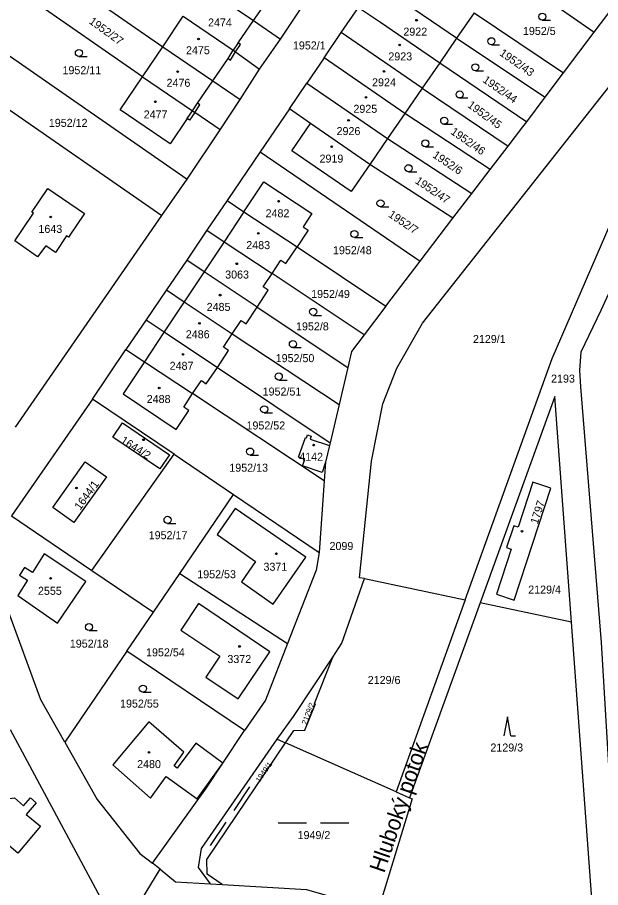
# Model space of a CAD drawing. Extents: x -679220 to -673243, y -1075091 to -1066557.
# Drawn here: x -676667.6 to -676543.7, y -1072885.5 to -1072700.8 of the extents above; entities that cross this region are included whole.
import ezdxf

# ---------------------------------------------------------------- set-up
doc = ezdxf.new("R2010")
doc.units = 0
for name, color, linetype in [('Hranice kat_území', 7, 'Continuous'), ('Hranice parcel', 7, 'Continuous'), ('Parcelní čísla', 7, 'Continuous'), ('Pop  PČ popisy', 7, 'Continuous'), ('Vnitřní kresba', 7, 'Continuous'), ('Značky budov', 7, 'Continuous'), ('Značky kultur', 7, 'Continuous')]:
    doc.layers.add(name, color=color, linetype=linetype)

msp = doc.modelspace()

# ---------------------------------------------------------------- linework, layer by layer
at = {"layer": 'Hranice kat_území'}
msp.add_line((-676626.56, -1072884.7), (-676624.07, -1072884.88), dxfattribs=at)
for points in [[(-676648.42, -1072899.8), (-676643.18, -1072891.41), (-676637.25, -1072881.62)], [(-676637.25, -1072881.62), (-676634, -1072884.28), (-676626.56, -1072884.7)], [(-676624.07, -1072884.88), (-676606.14, -1072885.94), (-676590.94, -1072890.3)]]:
    msp.add_lwpolyline(points, dxfattribs=at)
at = {"layer": 'Hranice parcel'}
for p, q in [((-676545.05, -1072703.94), (-676529.98, -1072683.88)), ((-676661.64, -1072689.7), (-676636.67, -1072707.03)), ((-676566.25, -1072689.13), (-676545.05, -1072703.94)), ((-676641, -1072713.4), (-676665.95, -1072696.04)), ((-676611.7, -1072705.39), (-676607.47, -1072699.05)), ((-676598.77, -1072704), (-676595.12, -1072698.65)), ((-676636.67, -1072707.03), (-676632.33, -1072700.52)), ((-676570.56, -1072699.78), (-676574.29, -1072705.21)), ((-676570.56, -1072699.78), (-676551.56, -1072712.54)), ((-676602.42, -1072709.36), (-676598.77, -1072704)), ((-676581.59, -1072715.82), (-676598.77, -1072704)), ((-676551.56, -1072712.54), (-676545.05, -1072703.94)), ((-676672.99, -1072706.39), (-676631.54, -1072735.13)), ((-676641, -1072713.4), (-676636.67, -1072707.03)), ((-676616.12, -1072711.79), (-676611.7, -1072705.39)), ((-676574.29, -1072705.21), (-676577.88, -1072710.43)), ((-676574.29, -1072705.21), (-676555.45, -1072717.68)), ((-676602.42, -1072709.36), (-676606.08, -1072714.73)), ((-676585.27, -1072721.17), (-676602.42, -1072709.36)), ((-676577.88, -1072710.43), (-676581.59, -1072715.82)), ((-676577.88, -1072710.43), (-676559.4, -1072722.91)), ((-676620.25, -1072718.2), (-676616.12, -1072711.79)), ((-676555.45, -1072717.68), (-676551.56, -1072712.54)), ((-676678.27, -1072714.14), (-676636.86, -1072742.81)), ((-676609.81, -1072720.21), (-676606.08, -1072714.73)), ((-676606.08, -1072714.73), (-676588.94, -1072726.51)), ((-676581.59, -1072715.82), (-676585.27, -1072721.17)), ((-676581.59, -1072715.82), (-676563.35, -1072728.09)), ((-676559.4, -1072722.91), (-676555.45, -1072717.68)), ((-676624.52, -1072724.61), (-676620.25, -1072718.2)), ((-676624.52, -1072724.61), (-676629.9, -1072720.95)), ((-676609.81, -1072720.21), (-676616.02, -1072729.34)), ((-676605.29, -1072723.32), (-676609.81, -1072720.21)), ((-676585.27, -1072721.17), (-676588.94, -1072726.51)), ((-676567.17, -1072733.09), (-676585.27, -1072721.17)), ((-676592.71, -1072731.98), (-676605.29, -1072723.32)), ((-676631.54, -1072735.13), (-676624.52, -1072724.61)), ((-676588.94, -1072726.51), (-676592.71, -1072731.98)), ((-676588.94, -1072726.51), (-676571.06, -1072738.18)), ((-676567.17, -1072733.09), (-676563.35, -1072728.09)), ((-676616.02, -1072729.34), (-676623.02, -1072739.65)), ((-676616.02, -1072729.34), (-676582.05, -1072752.56)), ((-676575.08, -1072743.43), (-676592.71, -1072731.98)), ((-676571.06, -1072738.18), (-676567.17, -1072733.09)), ((-676636.86, -1072742.81), (-676631.54, -1072735.13)), ((-676575.08, -1072743.43), (-676571.06, -1072738.18)), ((-676623.02, -1072739.65), (-676627.31, -1072745.97)), ((-676623.02, -1072739.65), (-676619.45, -1072742.02)), ((-676619.45, -1072742.02), (-676608.18, -1072749.51)), ((-676667.95, -1072787.75), (-676636.86, -1072742.81)), ((-676582.05, -1072752.56), (-676575.08, -1072743.43)), ((-676627.31, -1072745.97), (-676631.61, -1072752.3)), ((-676608.18, -1072749.51), (-676589.31, -1072762.05)), ((-676631.61, -1072752.3), (-676635.92, -1072758.64)), ((-676589.31, -1072762.05), (-676582.05, -1072752.56)), ((-676593.94, -1072768.16), (-676613.47, -1072755.18)), ((-676635.92, -1072758.64), (-676640.2, -1072764.96)), ((-676616.63, -1072762.29), (-676597.42, -1072775.1)), ((-676589.31, -1072762.05), (-676593.94, -1072768.16)), ((-676640.2, -1072764.96), (-676644.51, -1072771.31)), ((-676621.92, -1072767.93), (-676599.25, -1072782.97)), ((-676651.64, -1072781.8), (-676644.51, -1072771.31)), ((-676644.51, -1072771.31), (-676640.59, -1072773.9)), ((-676640.59, -1072773.9), (-676630.36, -1072780.66)), ((-676625.08, -1072775.07), (-676601.15, -1072791.08)), ((-676597.42, -1072775.1), (-676599.25, -1072782.97)), ((-676602.4, -1072799.14), (-676630.36, -1072780.66)), ((-676651.64, -1072781.8), (-676668.84, -1072806.61)), ((-676634.29, -1072793.54), (-676651.64, -1072781.8)), ((-676599.25, -1072782.97), (-676601.15, -1072791.08)), ((-676605.4, -1072790.31), (-676601.29, -1072791.69)), ((-676601.29, -1072791.69), (-676602.11, -1072795.21)), ((-676601.15, -1072791.08), (-676601.29, -1072791.69)), ((-676651.73, -1072818.21), (-676634.29, -1072793.54)), ((-676634.29, -1072793.54), (-676621.66, -1072802.09)), ((-676602.11, -1072795.21), (-676602.84, -1072797.38)), ((-676602.11, -1072795.21), (-676602.4, -1072799.14)), ((-676602.4, -1072799.14), (-676603.51, -1072814.38)), ((-676633.08, -1072818.86), (-676621.66, -1072802.09)), ((-676621.66, -1072802.09), (-676603.51, -1072814.38)), ((-676668.84, -1072806.61), (-676651.73, -1072818.21)), ((-676651.73, -1072818.21), (-676638.67, -1072827.06)), ((-676638.67, -1072827.06), (-676633.08, -1072818.86)), ((-676633.08, -1072818.86), (-676610.23, -1072833.74)), ((-676593.82, -1072819.93), (-676572.45, -1072824.42)), ((-676572.45, -1072824.42), (-676587.14, -1072865.18)), ((-676569.29, -1072825.08), (-676584.28, -1072866.45)), ((-676549.91, -1072829.16), (-676569.29, -1072825.08)), ((-676644.31, -1072835.34), (-676638.67, -1072827.06)), ((-676544.43, -1072903.83), (-676549.91, -1072829.16)), ((-676644.31, -1072835.34), (-676657.48, -1072854.68)), ((-676619.36, -1072852.17), (-676644.31, -1072835.34)), ((-676612.38, -1072854.04), (-676610.66, -1072854.8)), ((-676587.14, -1072865.18), (-676610.66, -1072854.8)), ((-676587.14, -1072865.18), (-676584.28, -1072866.45)), ((-676637.25, -1072881.62), (-676638.87, -1072880.32))]:
    msp.add_line(p, q, dxfattribs=at)
for points in [[(-676574.29, -1072705.21), (-676586.88, -1072696.55), (-676591.54, -1072693.39)], [(-676628.01, -1072694.22), (-676617.44, -1072701.46), (-676611.7, -1072705.39)], [(-676595.12, -1072698.65), (-676590.47, -1072701.78), (-676577.88, -1072710.43)], [(-676632.33, -1072700.52), (-676621.76, -1072707.76), (-676621.26, -1072708.1), (-676616.12, -1072711.79)], [(-676636.67, -1072707.03), (-676626.06, -1072714.25), (-676620.25, -1072718.2)], [(-676593.82, -1072819.93), (-676594.9, -1072819.74), (-676592.35, -1072795.01), (-676589.96, -1072782.82), (-676587.01, -1072775.23), (-676581.53, -1072765.66), (-676534.06, -1072705.55)], [(-676572.45, -1072824.42), (-676553.98, -1072773.19), (-676527.07, -1072711.02)], [(-676629.9, -1072720.95), (-676631, -1072722.56), (-676631.49, -1072722.23), (-676635.14, -1072727.59), (-676645.74, -1072720.38), (-676641, -1072713.4)], [(-676641, -1072713.4), (-676630.39, -1072720.62), (-676629.9, -1072720.95)], [(-676521.26, -1072714.56), (-676536.83, -1072748.24), (-676543.68, -1072763), (-676547.88, -1072771.84), (-676548.19, -1072775.66), (-676547.99, -1072779.21), (-676543.62, -1072833.49), (-676541.78, -1072863.16), (-676537.04, -1072892.63), (-676534.13, -1072903.67), (-676531.84, -1072907.69)], [(-676592.71, -1072731.98), (-676596.67, -1072737.74), (-676609.25, -1072729.08), (-676605.29, -1072723.32)], [(-676563.35, -1072728.09), (-676560.25, -1072724.03), (-676559.4, -1072722.91)], [(-676619.45, -1072742.02), (-676615.23, -1072735.65), (-676605.01, -1072742.43), (-676606.89, -1072745.26), (-676605.83, -1072745.96), (-676608.18, -1072749.51)], [(-676661.09, -1072737.1), (-676653.29, -1072742.44), (-676656.72, -1072747.46), (-676657.13, -1072747.18), (-676659.49, -1072750.66), (-676661.55, -1072749.26), (-676663.27, -1072751.6), (-676668.09, -1072748.23), (-676666.51, -1072745.81), (-676664.14, -1072742.34), (-676664.51, -1072742.09), (-676661.09, -1072737.1)], [(-676627.31, -1072745.97), (-676623.68, -1072748.39), (-676613.47, -1072755.18)], [(-676613.47, -1072755.18), (-676611.59, -1072752.35), (-676610.53, -1072753.05), (-676608.18, -1072749.51)], [(-676616.63, -1072762.29), (-676627.91, -1072754.77), (-676631.61, -1072752.3)], [(-676616.63, -1072762.29), (-676614.28, -1072758.71), (-676615.34, -1072758.01), (-676613.47, -1072755.18)], [(-676635.92, -1072758.64), (-676632.14, -1072761.15), (-676621.92, -1072767.93)], [(-676621.92, -1072767.93), (-676620.04, -1072765.1), (-676618.98, -1072765.8), (-676616.63, -1072762.29)], [(-676640.2, -1072764.96), (-676636.37, -1072767.52), (-676625.08, -1072775.07)], [(-676625.08, -1072775.07), (-676622.74, -1072771.46), (-676623.8, -1072770.76), (-676621.92, -1072767.93)], [(-676593.94, -1072768.16), (-676596.62, -1072771.69), (-676597.42, -1072775.1)], [(-676640.59, -1072773.9), (-676645.11, -1072780.71), (-676633.82, -1072788.29), (-676631.19, -1072784.21), (-676632.25, -1072783.51), (-676630.36, -1072780.66)], [(-676630.36, -1072780.66), (-676628.5, -1072777.85), (-676627.44, -1072778.55), (-676625.08, -1072775.07)], [(-676549.91, -1072829.16), (-676553.4, -1072781.23), (-676569.29, -1072825.08)], [(-676637.3, -1072796.6), (-676647.27, -1072789.89), (-676645.22, -1072786.88), (-676635.29, -1072793.63), (-676637.3, -1072796.6)], [(-676602.84, -1072797.38), (-676607, -1072795.98), (-676606.51, -1072794.61), (-676607.9, -1072794.11), (-676606.41, -1072789.96), (-676606.18, -1072790.04), (-676605.96, -1072789.43), (-676605.19, -1072789.68), (-676605.4, -1072790.31)], [(-676558.07, -1072799.45), (-676561.2, -1072809.04), (-676562.15, -1072808.73), (-676563.66, -1072813.34), (-676562.71, -1072813.65), (-676565.84, -1072823.24), (-676562.09, -1072824.47), (-676554.27, -1072800.74), (-676558.07, -1072799.45)], [(-676625.14, -1072810.57), (-676616.99, -1072816.29), (-676619.99, -1072820.64), (-676613.24, -1072825.34), (-676606.31, -1072815.39), (-676621.29, -1072805.01), (-676625.14, -1072810.57)], [(-676657.48, -1072854.68), (-676662.59, -1072845.67), (-676672.61, -1072818.42), (-676674.31, -1072814.63)], [(-676653.04, -1072820.52), (-676661.87, -1072814.7), (-676664.39, -1072818.66), (-676666.09, -1072817.58), (-676667.1, -1072819.18), (-676665.4, -1072820.26), (-676667.48, -1072823.53), (-676659.05, -1072829.38), (-676653.04, -1072820.52)], [(-676603.51, -1072814.38), (-676604.14, -1072818.11), (-676610.23, -1072833.74)], [(-676600.58, -1072836.58), (-676598.67, -1072833.66), (-676593.82, -1072819.93)], [(-676627.57, -1072840.88), (-676620.69, -1072845.47), (-676613.96, -1072835.46), (-676629.1, -1072825.24), (-676632.87, -1072830.87), (-676624.58, -1072836.4), (-676627.57, -1072840.88)], [(-676610.23, -1072833.74), (-676614.88, -1072845.71), (-676619.36, -1072852.17)], [(-676612.38, -1072854.04), (-676608.9, -1072849.18), (-676600.58, -1072836.58)], [(-676610.66, -1072854.8), (-676608.87, -1072852.15), (-676606.51, -1072852.11), (-676604.22, -1072846.49), (-676604.46, -1072846.44), (-676600.58, -1072836.58)], [(-676632.2, -1072856.81), (-676639.64, -1072850.31), (-676647.28, -1072859.5), (-676639.32, -1072866.57)], [(-676669.1, -1072851.93), (-676648.4, -1072890.46), (-676657.67, -1072902.92)], [(-676638.87, -1072880.32), (-676627.4, -1072864.33), (-676623.93, -1072859.09), (-676619.36, -1072852.17)], [(-676657.48, -1072854.68), (-676650.59, -1072866.83), (-676641.58, -1072878.26), (-676638.87, -1072880.32)], [(-676629.69, -1072854.84), (-676633.63, -1072860.19), (-676634.27, -1072859.71), (-676632.2, -1072856.81)], [(-676629.42, -1072866.71), (-676623.93, -1072859.09), (-676629.69, -1072854.84)], [(-676626.56, -1072884.7), (-676629.13, -1072881.23), (-676628.48, -1072877.23), (-676612.38, -1072854.04)], [(-676624.07, -1072884.88), (-676627.26, -1072882.71), (-676627.36, -1072879.59), (-676610.66, -1072854.8)], [(-676639.32, -1072866.57), (-676635.95, -1072861.95), (-676629.42, -1072866.71)], [(-676675.53, -1072868.64), (-676672.11, -1072864.65), (-676669.69, -1072866.66), (-676668.17, -1072866.46), (-676666.26, -1072868.17), (-676664.78, -1072866.45), (-676663.55, -1072867.5), (-676665.69, -1072869.99), (-676662.68, -1072872.49), (-676667.49, -1072878.19), (-676670.39, -1072875.75), (-676671.83, -1072875.84), (-676674.43, -1072878.94), (-676680.15, -1072874.17), (-676678.92, -1072872.66), (-676678.89, -1072871.16), (-676677.01, -1072868.92), (-676675.53, -1072868.64)], [(-676584.28, -1072866.45), (-676583.69, -1072866.71), (-676590.94, -1072890.3)]]:
    msp.add_lwpolyline(points, dxfattribs=at)
at = {"layer": 'Vnitřní kresba'}
for p, q in [((-676617.44, -1072701.46), (-676614.21, -1072696.83)), ((-676620.67, -1072706.18), (-676617.44, -1072701.46)), ((-676620.67, -1072706.18), (-676621.76, -1072707.76)), ((-676621.26, -1072708.1), (-676620.18, -1072706.52)), ((-676620.18, -1072706.52), (-676620.67, -1072706.18)), ((-676622.83, -1072709.5), (-676621.76, -1072707.76)), ((-676622.34, -1072709.84), (-676621.26, -1072708.1)), ((-676626.06, -1072714.25), (-676622.83, -1072709.5)), ((-676622.83, -1072709.5), (-676622.34, -1072709.84)), ((-676629.3, -1072719.01), (-676626.06, -1072714.25)), ((-676630.39, -1072720.62), (-676629.3, -1072719.01)), ((-676629.9, -1072720.95), (-676628.81, -1072719.34)), ((-676628.81, -1072719.34), (-676629.3, -1072719.01)), ((-676631.49, -1072722.23), (-676630.39, -1072720.62)), ((-676619.45, -1072742.02), (-676623.68, -1072748.39)), ((-676623.68, -1072748.39), (-676627.91, -1072754.77)), ((-676627.91, -1072754.77), (-676632.14, -1072761.15)), ((-676632.14, -1072761.15), (-676636.37, -1072767.52)), ((-676636.37, -1072767.52), (-676640.59, -1072773.9)), ((-676660.07, -1072804.85), (-676653.2, -1072795.1)), ((-676653.2, -1072795.1), (-676648.67, -1072798.32)), ((-676648.67, -1072798.32), (-676655.55, -1072808.04)), ((-676655.55, -1072808.04), (-676660.07, -1072804.85))]:
    msp.add_line(p, q, dxfattribs=at)
at = {"layer": 'Značky budov'}
for centre in [(-676582.79, -1072701.37), (-676629.09, -1072705.36), (-676586.37, -1072706.62), (-676633.53, -1072712.29), (-676589.69, -1072712.25), (-676593.53, -1072717.75), (-676638.28, -1072718.69), (-676597.23, -1072722.61), (-676600.81, -1072728.23), (-676612.08, -1072739.8), (-676660.49, -1072743.15), (-676616.4, -1072746.63), (-676620.97, -1072753.09), (-676624.51, -1072759.74), (-676628.9, -1072765.71), (-676632.38, -1072772.31), (-676637.44, -1072779.45), (-676640.79, -1072790.45), (-676604.66, -1072791.59), (-676655.02, -1072800.7), (-676560.4, -1072809.87), (-676612.56, -1072814.66), (-676660.5, -1072819.87), (-676620.39, -1072834.34), (-676639.6, -1072856.82)]:
    msp.add_circle(centre, 0.175, dxfattribs=at)
at = {"layer": 'Značky kultur'}
for p, q in [((-676556.09, -1072701.36), (-676554.34, -1072701.36)), ((-676566.9, -1072706.58), (-676565.15, -1072706.58)), ((-676654.51, -1072709.07), (-676652.76, -1072709.07)), ((-676570.3, -1072712.11), (-676568.55, -1072712.11)), ((-676573.64, -1072717.88), (-676571.89, -1072717.88)), ((-676576.92, -1072723.47), (-676575.17, -1072723.47)), ((-676580.92, -1072728.26), (-676579.17, -1072728.26)), ((-676584.5, -1072733.55), (-676582.75, -1072733.55)), ((-676590.45, -1072740.99), (-676588.7, -1072740.99)), ((-676595.98, -1072747.51), (-676594.23, -1072747.51)), ((-676604.75, -1072764.03), (-676603, -1072764.03)), ((-676609.06, -1072770.89), (-676607.31, -1072770.89)), ((-676612.05, -1072777.76), (-676610.3, -1072777.76)), ((-676615.15, -1072784.73), (-676613.4, -1072784.73)), ((-676618.14, -1072793.7), (-676616.39, -1072793.7)), ((-676635.67, -1072808.2), (-676633.92, -1072808.2)), ((-676652.35, -1072830.96), (-676650.6, -1072830.96)), ((-676640.92, -1072844.03), (-676639.17, -1072844.03)), ((-676563.5, -1072849.28), (-676564.25, -1072853.28)), ((-676562.75, -1072853.28), (-676563.5, -1072849.28)), ((-676562.75, -1072853.28), (-676561.75, -1072853.28)), ((-676621.54, -1072869.13), (-676618.18, -1072864.15)), ((-676626.57, -1072876.59), (-676623.21, -1072871.61)), ((-676612.17, -1072871.79), (-676606.17, -1072871.79)), ((-676603.17, -1072871.79), (-676597.17, -1072871.79))]:
    msp.add_line(p, q, dxfattribs=at)
for centre in [(-676556.09, -1072700.61), (-676566.9, -1072705.83), (-676654.51, -1072708.32), (-676570.3, -1072711.36), (-676573.64, -1072717.13), (-676576.92, -1072722.72), (-676580.92, -1072727.51), (-676584.5, -1072732.8), (-676590.45, -1072740.24), (-676595.98, -1072746.76), (-676604.75, -1072763.28), (-676609.06, -1072770.14), (-676612.05, -1072777.01), (-676615.15, -1072783.98), (-676618.14, -1072792.95), (-676635.67, -1072807.45), (-676652.35, -1072830.21), (-676640.92, -1072843.28)]:
    msp.add_circle(centre, 0.75, dxfattribs=at)

# ---------------------------------------------------------------- texts
at = {"layer": 'Parcelní čísla'}
for s, height, rotation, p in [('1952/27', 1.7, 324, (-676652.5, -1072701.92)), ('1952/43', 1.7, 325, (-676565.31, -1072708.7)), ('1952/44', 1.7, 325, (-676568.89, -1072714.38)), ('1952/45', 1.7, 324, (-676572.12, -1072719.7)), ('1952/46', 1.7, 325, (-676575.69, -1072725.39)), ('1952/6', 1.7, 326, (-676579.53, -1072730.37)), ('1952/47', 1.7, 326, (-676583.24, -1072735.84)), ('1952/7', 1.7, 326, (-676588.93, -1072742.99)), ('1644/2', 1.7, 328, (-676645.8, -1072791.01)), ('1644/1', 1.7, 54, (-676654.22, -1072805.5)), ('1797', 1.7, 72, (-676557.07, -1072808.49)), ('2129/2', 1.14, 69, (-676606.18, -1072851.02)), ('1949/1', 1.14, 55, (-676616.15, -1072863.29))]:
    msp.add_text(s, height=height, rotation=rotation, dxfattribs=at).set_placement(p)
for s, p in [('2474', (-676627.08, -1072702.7)), ('2922', (-676585.59, -1072704.65)), ('1952/5', (-676560.2, -1072704.5)), ('2475', (-676631.76, -1072708.59)), ('1952/1', (-676609.05, -1072707.57)), ('2923', (-676588.78, -1072709.9)), ('1952/11', (-676657.99, -1072712.83)), ('2476', (-676635.89, -1072715.51)), ('2924', (-676592.24, -1072715.4)), ('2925', (-676596.2, -1072721.03)), ('2477', (-676640.75, -1072722.23)), ('1952/12', (-676660.89, -1072724.01)), ('2926', (-676599.78, -1072725.76)), ('2919', (-676603.4, -1072731.6)), ('2482', (-676614.86, -1072743.21)), ('1643', (-676663.1, -1072746.53)), ('2483', (-676618.96, -1072749.97)), ('1952/48', (-676600.54, -1072751.05)), ('3063', (-676623.44, -1072756.22)), ('1952/49', (-676605.18, -1072760.35)), ('2485', (-676627.37, -1072763.09)), ('1952/8', (-676608.39, -1072767.22)), ('2486', (-676631.8, -1072768.9)), ('2129/1', (-676570.82, -1072769.91)), ('1952/50', (-676612.71, -1072773.97)), ('2487', (-676635.23, -1072775.6)), ('2193', (-676554.22, -1072778.31)), ('2488', (-676640.1, -1072782.64)), ('1952/51', (-676615.48, -1072781.06)), ('1952/52', (-676618.91, -1072788.26)), ('4142', (-676607.71, -1072794.91)), ('1952/13', (-676622.56, -1072797.23)), ('1952/17', (-676639.68, -1072811.56)), ('2099', (-676601.28, -1072813.86)), ('3371', (-676615.3, -1072818.26)), ('1952/53', (-676629.37, -1072819.85)), ('2129/4', (-676559.08, -1072823.11)), ('2555', (-676663.2, -1072823.37)), ('1952/18', (-676656.43, -1072834.58)), ('1952/54', (-676640.24, -1072836.43)), ('3372', (-676622.97, -1072837.85)), ('2129/6', (-676593.16, -1072842.3)), ('1952/55', (-676645.76, -1072847.31)), ('2129/3', (-676567.11, -1072856.64)), ('2480', (-676642.14, -1072860.16)), ('1949/2', (-676608.06, -1072875.23))]:
    msp.add_text(s, height=1.7, dxfattribs=at).set_placement(p)
at = {"layer": 'Pop  PČ popisy'}
msp.add_text('Hluboký potok', height=3.4, rotation=71, dxfattribs=at).set_placement((-676589.68, -1072882.59))

doc.saveas('drawing.dxf')
